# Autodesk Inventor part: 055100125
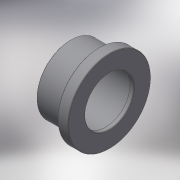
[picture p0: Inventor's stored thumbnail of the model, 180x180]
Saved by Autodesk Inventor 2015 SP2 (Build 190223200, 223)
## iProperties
Created: 2017-10
Part Number: 055100125
Material: Generic
Description: PLASSON FLANGE FLAT AD.-CEM 125
Document SubType Name: Modeling
Designer: KIM
Mass: 404.249 g
Surface Area: 873.663 cm^2
Volume: 404.249 cm^3
Density: 1 g/cm^3
Appearance: Default
Author: KIM
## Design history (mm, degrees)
derived "055100.ipt"
feature "Solid1::055100.ipt"
tag "TaggingFeature1"
body "Solid1"
other parameters: "d0" = 74, "d1" = 146, "d2" = 125, "d3" = 112.5, "d4" = 11, "d5" = 69, "d6" = 169, "d8" = 1.25, "d_" = 125, "E_" = 146, "E_1" = 169, "l_" = 69, "B_" = 11, "H_" = 74
